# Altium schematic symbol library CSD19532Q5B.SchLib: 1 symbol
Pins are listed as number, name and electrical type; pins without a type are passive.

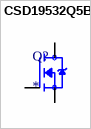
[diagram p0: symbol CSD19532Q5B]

## CSD19532Q5B
designator Q?
100-V, N channel NexFETâ„¢ power MOSFET, single SON 5 mm x 6 mm, 4.9 mOhm; MF: Texas Instruments; MP: CSD19532Q5B
footprint TRANS_CSD19532Q5B
pins: 1 S, 2 S, 3 S, 4 G, 5_8 D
